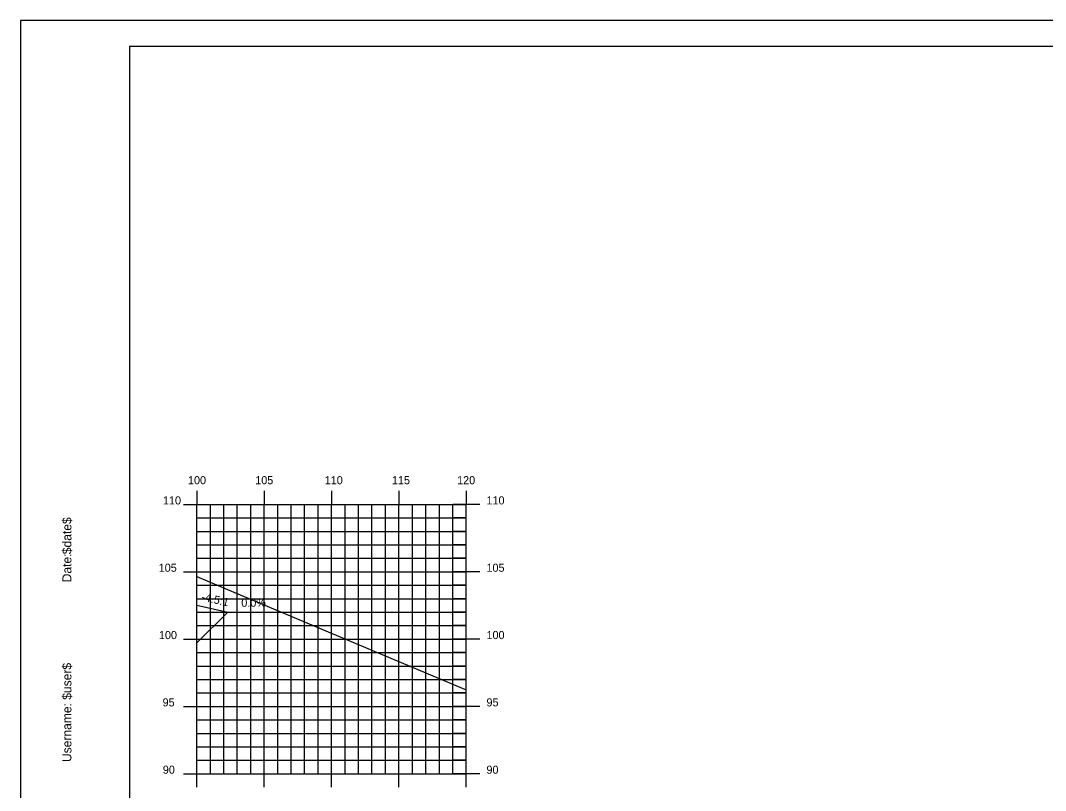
# Model space of a CAD drawing. Extents: x 850598 to 870284, y 366541 to 366651.
# Drawn here: x 856141.7 to 856217.8, y 366594 to 366651.2 of the extents above; entities that cross this region are included whole.
import ezdxf

# ---------------------------------------------------------------- set-up
doc = ezdxf.new("R2010")
doc.units = 0
for name, color, linetype in [('ANNOTATION', 7, 'Continuous'), ('BORDER', 7, 'Continuous'), ('D_Drainage_RipRap', 7, 'Continuous'), ('D_Roadway_Centerline', 7, 'Continuous'), ('D_Roadway_SlopeLines', 7, 'Continuous'), ('H_V ANNOTATION', 7, 'Continuous'), ('MAJOR', 7, 'Continuous'), ('MINOR', 7, 'Continuous'), ('PLOT BOUNDARY', 7, 'Continuous'), ('S_Roadway_Centerline', 7, 'Continuous')]:
    doc.layers.add(name, color=color, linetype=linetype)

msp = doc.modelspace()

# ---------------------------------------------------------------- linework, layer by layer
at = {"layer": 'BORDER'}
for p, q in [((856309.811, 366649.225), (856149.811, 366649.225)), ((856149.811, 366649.225), (856149.811, 366544.225))]:
    msp.add_line(p, q, dxfattribs=at)
at = {"layer": 'D_Drainage_RipRap'}
msp.add_lwpolyline([(856154.811, 366604.934), (856154.811, 366607.738), (856157.102, 366607.225)], close=True, dxfattribs=at)
at = {"layer": 'D_Roadway_Centerline'}
msp.add_lwpolyline([(856154.811, 366607.738), (856157.102, 366607.225), (856161.102, 366607.225)], dxfattribs=at)
at = {"layer": 'D_Roadway_SlopeLines'}
msp.add_lwpolyline([(856154.811, 366607.738), (856157.102, 366607.225)], dxfattribs=at)
at = {"layer": 'MAJOR'}
for p, q in [((856154.811, 366616.227), (856154.811, 366615.225)), ((856154.811, 366616.227), (856154.811, 366615.225)), ((856159.811, 366616.227), (856159.811, 366615.225)), ((856159.811, 366616.227), (856159.811, 366615.225)), ((856164.811, 366616.227), (856164.811, 366615.225)), ((856164.811, 366616.227), (856164.811, 366615.225)), ((856169.811, 366616.227), (856169.811, 366615.225)), ((856169.811, 366616.227), (856169.811, 366615.225)), ((856174.811, 366616.227), (856174.811, 366615.225)), ((856174.811, 366616.227), (856174.811, 366615.225)), ((856153.809, 366615.225), (856154.811, 366615.225)), ((856153.809, 366615.225), (856154.811, 366615.225)), ((856154.811, 366615.225), (856174.811, 366615.225)), ((856154.811, 366595.225), (856154.811, 366615.225)), ((856154.811, 366595.225), (856154.811, 366615.225)), ((856154.811, 366615.225), (856174.811, 366615.225)), ((856154.811, 366615.225), (856174.811, 366615.225)), ((856154.811, 366595.225), (856154.811, 366615.225)), ((856154.811, 366595.225), (856154.811, 366615.225)), ((856154.811, 366615.225), (856174.811, 366615.225)), ((856159.811, 366595.225), (856159.811, 366615.225)), ((856159.811, 366595.225), (856159.811, 366615.225)), ((856164.811, 366595.225), (856164.811, 366615.225)), ((856164.811, 366595.225), (856164.811, 366615.225)), ((856169.811, 366595.225), (856169.811, 366615.225)), ((856169.811, 366595.225), (856169.811, 366615.225)), ((856175.813, 366615.225), (856173.809, 366615.225)), ((856175.813, 366615.225), (856173.809, 366615.225)), ((856174.811, 366595.225), (856174.811, 366615.225)), ((856174.811, 366595.225), (856174.811, 366615.225)), ((856174.811, 366595.225), (856174.811, 366615.225)), ((856174.811, 366595.225), (856174.811, 366615.225)), ((856153.809, 366610.225), (856154.811, 366610.225)), ((856153.809, 366610.225), (856154.811, 366610.225)), ((856154.811, 366610.225), (856174.811, 366610.225)), ((856154.811, 366610.225), (856174.811, 366610.225)), ((856175.813, 366610.225), (856173.809, 366610.225)), ((856175.813, 366610.225), (856173.809, 366610.225)), ((856153.809, 366605.225), (856154.811, 366605.225)), ((856153.809, 366605.225), (856154.811, 366605.225)), ((856154.811, 366605.225), (856174.811, 366605.225)), ((856154.811, 366605.225), (856174.811, 366605.225)), ((856175.813, 366605.225), (856173.809, 366605.225)), ((856175.813, 366605.225), (856173.809, 366605.225)), ((856153.809, 366600.225), (856154.811, 366600.225)), ((856153.809, 366600.225), (856154.811, 366600.225)), ((856154.811, 366600.225), (856174.811, 366600.225)), ((856154.811, 366600.225), (856174.811, 366600.225)), ((856175.813, 366600.225), (856173.809, 366600.225)), ((856175.813, 366600.225), (856173.809, 366600.225)), ((856153.809, 366595.225), (856154.811, 366595.225)), ((856153.809, 366595.225), (856154.811, 366595.225)), ((856154.811, 366595.225), (856174.811, 366595.225)), ((856154.811, 366595.225), (856174.811, 366595.225)), ((856154.811, 366594.223), (856154.811, 366595.225)), ((856154.811, 366595.225), (856174.811, 366595.225)), ((856154.811, 366595.225), (856174.811, 366595.225)), ((856154.811, 366594.223), (856154.811, 366595.225)), ((856159.811, 366594.223), (856159.811, 366595.225)), ((856159.811, 366594.223), (856159.811, 366595.225)), ((856164.811, 366594.223), (856164.811, 366595.225)), ((856164.811, 366594.223), (856164.811, 366595.225)), ((856169.811, 366594.223), (856169.811, 366595.225)), ((856169.811, 366594.223), (856169.811, 366595.225)), ((856175.813, 366595.225), (856173.809, 366595.225)), ((856175.813, 366595.225), (856173.809, 366595.225)), ((856174.811, 366594.223), (856174.811, 366595.225)), ((856174.811, 366594.223), (856174.811, 366595.225))]:
    msp.add_line(p, q, dxfattribs=at)
at = {"layer": 'MINOR'}
for p, q in [((856155.811, 366595.225), (856155.811, 366615.225)), ((856155.811, 366595.225), (856155.811, 366615.225)), ((856156.811, 366595.225), (856156.811, 366615.225)), ((856156.811, 366595.225), (856156.811, 366615.225)), ((856157.811, 366595.225), (856157.811, 366615.225)), ((856157.811, 366595.225), (856157.811, 366615.225)), ((856158.811, 366595.225), (856158.811, 366615.225)), ((856158.811, 366595.225), (856158.811, 366615.225)), ((856160.811, 366595.225), (856160.811, 366615.225)), ((856160.811, 366595.225), (856160.811, 366615.225)), ((856161.811, 366595.225), (856161.811, 366615.225)), ((856161.811, 366595.225), (856161.811, 366615.225)), ((856162.811, 366595.225), (856162.811, 366615.225)), ((856162.811, 366595.225), (856162.811, 366615.225)), ((856163.811, 366595.225), (856163.811, 366615.225)), ((856163.811, 366595.225), (856163.811, 366615.225)), ((856165.811, 366595.225), (856165.811, 366615.225)), ((856165.811, 366595.225), (856165.811, 366615.225)), ((856166.811, 366595.225), (856166.811, 366615.225)), ((856166.811, 366595.225), (856166.811, 366615.225)), ((856167.811, 366595.225), (856167.811, 366615.225)), ((856167.811, 366595.225), (856167.811, 366615.225)), ((856168.811, 366595.225), (856168.811, 366615.225)), ((856168.811, 366595.225), (856168.811, 366615.225)), ((856170.811, 366595.225), (856170.811, 366615.225)), ((856170.811, 366595.225), (856170.811, 366615.225)), ((856171.811, 366595.225), (856171.811, 366615.225)), ((856171.811, 366595.225), (856171.811, 366615.225)), ((856172.811, 366595.225), (856172.811, 366615.225)), ((856172.811, 366595.225), (856172.811, 366615.225)), ((856173.811, 366595.225), (856173.811, 366615.225)), ((856173.811, 366595.225), (856173.811, 366615.225)), ((856154.811, 366614.225), (856174.811, 366614.225)), ((856154.811, 366614.225), (856155.813, 366614.225)), ((856154.811, 366614.225), (856174.811, 366614.225)), ((856154.811, 366614.225), (856155.813, 366614.225)), ((856174.811, 366614.225), (856173.809, 366614.225)), ((856174.811, 366614.225), (856173.809, 366614.225)), ((856154.811, 366613.225), (856174.811, 366613.225)), ((856154.811, 366613.225), (856155.813, 366613.225)), ((856154.811, 366613.225), (856174.811, 366613.225)), ((856154.811, 366613.225), (856155.813, 366613.225)), ((856174.811, 366613.225), (856173.809, 366613.225)), ((856174.811, 366613.225), (856173.809, 366613.225)), ((856154.811, 366612.225), (856174.811, 366612.225)), ((856154.811, 366612.225), (856155.813, 366612.225)), ((856154.811, 366612.225), (856174.811, 366612.225)), ((856154.811, 366612.225), (856155.813, 366612.225)), ((856174.811, 366612.225), (856173.809, 366612.225)), ((856174.811, 366612.225), (856173.809, 366612.225)), ((856154.811, 366611.225), (856174.811, 366611.225)), ((856154.811, 366611.225), (856155.813, 366611.225)), ((856154.811, 366611.225), (856174.811, 366611.225)), ((856154.811, 366611.225), (856155.813, 366611.225)), ((856174.811, 366611.225), (856173.809, 366611.225)), ((856174.811, 366611.225), (856173.809, 366611.225)), ((856154.811, 366609.225), (856174.811, 366609.225)), ((856154.811, 366609.225), (856155.813, 366609.225)), ((856154.811, 366609.225), (856174.811, 366609.225)), ((856154.811, 366609.225), (856155.813, 366609.225)), ((856174.811, 366609.225), (856173.809, 366609.225)), ((856174.811, 366609.225), (856173.809, 366609.225)), ((856154.811, 366608.225), (856174.811, 366608.225)), ((856154.811, 366608.225), (856155.813, 366608.225)), ((856154.811, 366608.225), (856174.811, 366608.225)), ((856154.811, 366608.225), (856155.813, 366608.225)), ((856174.811, 366608.225), (856173.809, 366608.225)), ((856174.811, 366608.225), (856173.809, 366608.225)), ((856154.811, 366607.225), (856174.811, 366607.225)), ((856154.811, 366607.225), (856155.813, 366607.225)), ((856154.811, 366607.225), (856174.811, 366607.225)), ((856154.811, 366607.225), (856155.813, 366607.225)), ((856174.811, 366607.225), (856173.809, 366607.225)), ((856174.811, 366607.225), (856173.809, 366607.225)), ((856154.811, 366606.225), (856174.811, 366606.225)), ((856154.811, 366606.225), (856155.813, 366606.225)), ((856154.811, 366606.225), (856174.811, 366606.225)), ((856154.811, 366606.225), (856155.813, 366606.225)), ((856174.811, 366606.225), (856173.809, 366606.225)), ((856174.811, 366606.225), (856173.809, 366606.225)), ((856154.811, 366604.225), (856174.811, 366604.225)), ((856154.811, 366604.225), (856155.813, 366604.225)), ((856154.811, 366604.225), (856174.811, 366604.225)), ((856154.811, 366604.225), (856155.813, 366604.225)), ((856174.811, 366604.225), (856173.809, 366604.225)), ((856174.811, 366604.225), (856173.809, 366604.225)), ((856154.811, 366603.225), (856174.811, 366603.225)), ((856154.811, 366603.225), (856155.813, 366603.225)), ((856154.811, 366603.225), (856174.811, 366603.225)), ((856154.811, 366603.225), (856155.813, 366603.225)), ((856174.811, 366603.225), (856173.809, 366603.225)), ((856174.811, 366603.225), (856173.809, 366603.225)), ((856154.811, 366602.225), (856174.811, 366602.225)), ((856154.811, 366602.225), (856155.813, 366602.225)), ((856154.811, 366602.225), (856174.811, 366602.225)), ((856154.811, 366602.225), (856155.813, 366602.225)), ((856174.811, 366602.225), (856173.809, 366602.225)), ((856174.811, 366602.225), (856173.809, 366602.225)), ((856154.811, 366601.225), (856174.811, 366601.225)), ((856154.811, 366601.225), (856155.813, 366601.225)), ((856154.811, 366601.225), (856174.811, 366601.225)), ((856154.811, 366601.225), (856155.813, 366601.225)), ((856174.811, 366601.225), (856173.809, 366601.225)), ((856174.811, 366601.225), (856173.809, 366601.225)), ((856154.811, 366599.225), (856174.811, 366599.225)), ((856154.811, 366599.225), (856155.813, 366599.225)), ((856154.811, 366599.225), (856174.811, 366599.225)), ((856154.811, 366599.225), (856155.813, 366599.225)), ((856174.811, 366599.225), (856173.809, 366599.225)), ((856174.811, 366599.225), (856173.809, 366599.225)), ((856154.811, 366598.225), (856174.811, 366598.225)), ((856154.811, 366598.225), (856155.813, 366598.225)), ((856154.811, 366598.225), (856174.811, 366598.225)), ((856154.811, 366598.225), (856155.813, 366598.225)), ((856174.811, 366598.225), (856173.809, 366598.225)), ((856174.811, 366598.225), (856173.809, 366598.225)), ((856154.811, 366597.225), (856174.811, 366597.225)), ((856154.811, 366597.225), (856155.813, 366597.225)), ((856154.811, 366597.225), (856174.811, 366597.225)), ((856154.811, 366597.225), (856155.813, 366597.225)), ((856174.811, 366597.225), (856173.809, 366597.225)), ((856174.811, 366597.225), (856173.809, 366597.225)), ((856154.811, 366596.225), (856174.811, 366596.225)), ((856154.811, 366596.225), (856155.813, 366596.225)), ((856154.811, 366596.225), (856174.811, 366596.225)), ((856154.811, 366596.225), (856155.813, 366596.225)), ((856174.811, 366596.225), (856173.809, 366596.225)), ((856174.811, 366596.225), (856173.809, 366596.225))]:
    msp.add_line(p, q, dxfattribs=at)
at = {"layer": 'PLOT BOUNDARY'}
msp.add_lwpolyline([(856141.717, 366541.166), (856311.717, 366541.166), (856311.717, 366651.166), (856141.717, 366651.166)], close=True, dxfattribs=at)
at = {"layer": 'S_Roadway_Centerline'}
msp.add_lwpolyline([(856154.811, 366609.884), (856157.073, 366608.918), (856174.811, 366601.468)], dxfattribs=at)

# ---------------------------------------------------------------- texts
at = {"layer": 'ANNOTATION'}
msp.add_text('-4.5:1', height=0.6, rotation=347.38208, dxfattribs=at).set_placement((856155.108, 366608.097))
msp.add_text('0.0%', height=0.6, dxfattribs=at).set_placement((856158.107, 366607.625))
at = {"layer": 'BORDER'}
for s, p in [('$date$', (856145.496, 366611.53)), ('Date:', (856145.496, 366609.442)), ('$user$', (856145.496, 366600.717)), ('Username:', (856145.496, 366596.093))]:
    msp.add_text(s, height=0.6696, rotation=90, dxfattribs=at).set_placement(p)
at = {"layer": 'H_V ANNOTATION'}
for s, p in [('100', (856154.152, 366616.725)), ('105', (856159.144, 366616.725)), ('110', (856164.302, 366616.725)), ('115', (856169.294, 366616.725)), ('120', (856174.131, 366616.725)), ('110', (856152.294, 366615.225)), ('110', (856176.311, 366615.225)), ('105', (856151.978, 366610.225)), ('105', (856176.311, 366610.225)), ('100', (856151.994, 366605.225)), ('100', (856176.311, 366605.225)), ('95', (856152.267, 366600.225)), ('95', (856176.311, 366600.225)), ('90', (856152.283, 366595.225)), ('90', (856176.311, 366595.225))]:
    msp.add_text(s, height=0.6, dxfattribs=at).set_placement(p)

doc.saveas('drawing.dxf')
